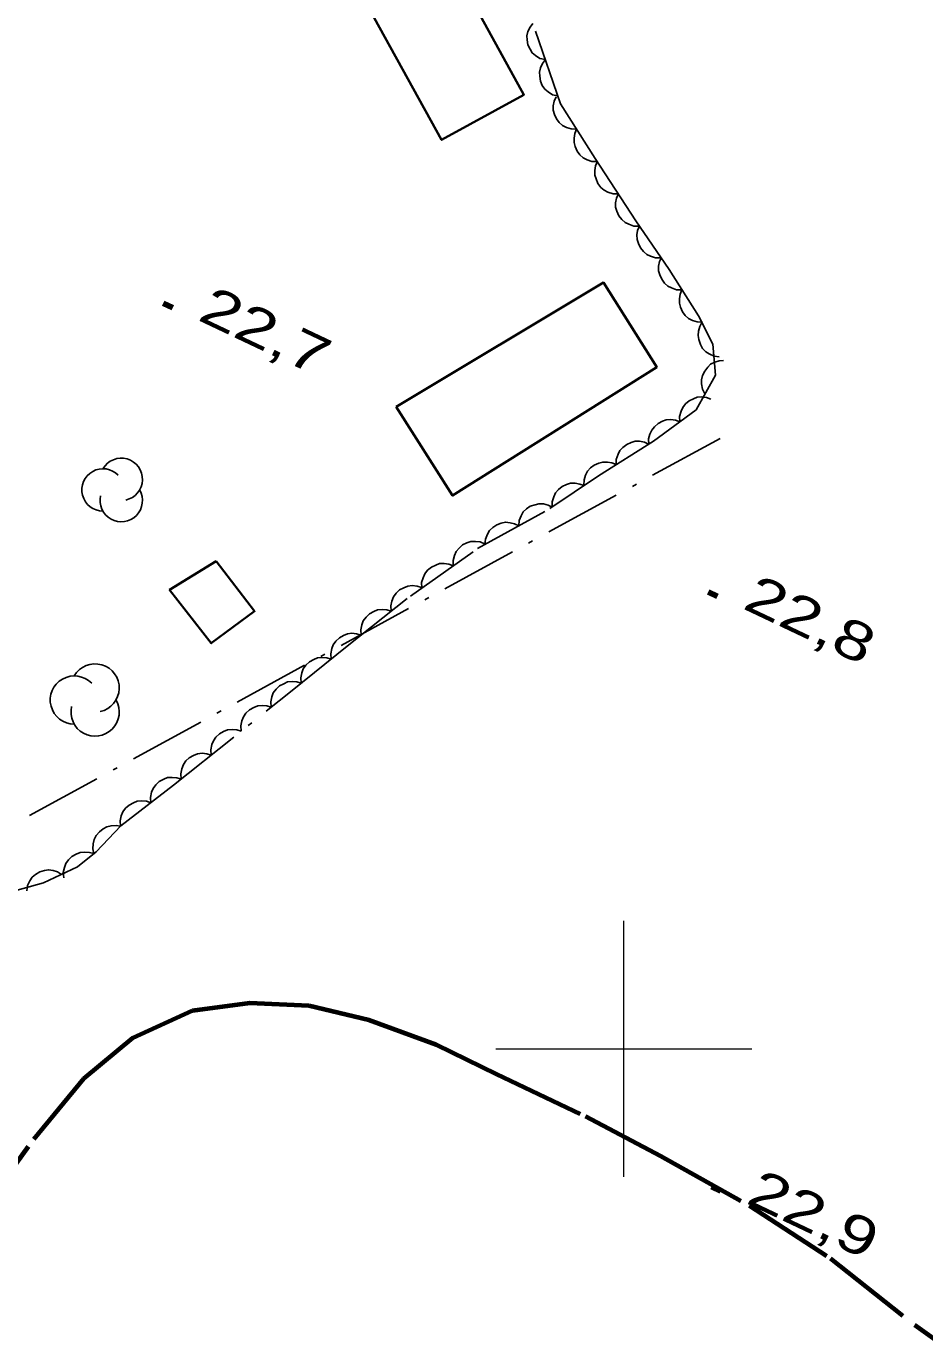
# Model space of a CAD drawing. Extents: x 356765 to 358572, y 5103174 to 5104650.
# Drawn here: x 357076.7 to 357111.7, y 5104088.5 to 5104139.9 of the extents above; entities that cross this region are included whole.
import ezdxf

# ---------------------------------------------------------------- set-up
doc = ezdxf.new("R2010")
doc.units = 0
doc.header["$LTSCALE"] = 0.6
doc.linetypes.add('DOT_DASHED', pattern=[7.7, 5, -1.2, 0.3, -1.2])
doc.linetypes.add('LONG_DASHED', pattern=[7.5, 6, -1.5])
for name, color, linetype, lineweight in [('22', 7, 'Continuous', 35), ('3', 7, 'Continuous', 140), ('31', 7, 'Continuous', 70), ('41', 7, 'DOT_DASHED', 25), ('44', 7, 'Continuous', 25), ('61', 7, 'Continuous', 13)]:
    doc.layers.add(name, color=color, linetype=linetype, lineweight=lineweight)

msp = doc.modelspace()

# ---------------------------------------------------------------- linework, layer by layer
at = {"layer": '22', "linetype": 'LONG_DASHED', "lineweight": 70}
msp.add_lwpolyline([(357070.45, 5104087.71), (357072.96, 5104090.8), (357074.65, 5104093.26), (357076.97, 5104096.47), (357078.92, 5104098.83), (357080.84, 5104100.43), (357083.17, 5104101.49), (357085.4, 5104101.79), (357087.7, 5104101.69), (357090.05, 5104101.13), (357092.68, 5104100.16), (357095.05, 5104099.01), (357098.51, 5104097.36), (357101.43, 5104095.82), (357104.9, 5104093.87), (357108.07, 5104091.8), (357111.35, 5104089.21), (357113.03, 5104088.01)], dxfattribs=at)
at = {"layer": '3'}
for p, q in [((357082.02, 5104129.12), (357082.38, 5104128.95)), ((357103.29, 5104117.85), (357103.65, 5104117.68)), ((357103.42, 5104094.62), (357103.78, 5104094.45))]:
    msp.add_line(p, q, dxfattribs=at)
at = {"layer": '31', "lineweight": 35}
for points in [[(357089.36, 5104141.91), (357092.89, 5104135.5), (357096.1, 5104137.27), (357092.58, 5104143.67), (357089.36, 5104141.91)], [(357091.11, 5104125.08), (357099.21, 5104129.93), (357101.29, 5104126.63), (357093.32, 5104121.61), (357091.11, 5104125.08)], [(357084.09, 5104119.05), (357085.59, 5104117.09), (357083.9, 5104115.84), (357082.27, 5104117.92), (357084.09, 5104119.05)]]:
    msp.add_lwpolyline(points, close=True, dxfattribs=at)
at = {"layer": '41'}
msp.add_line((357103.76, 5104123.84), (357040.83, 5104089.45), dxfattribs=at)
at = {"layer": '44', "linetype": 'DOT_DASHED'}
msp.add_lwpolyline([(357075.25, 5104105.89), (357077.35, 5104106.48), (357078.68, 5104107.11), (357079.4, 5104107.69), (357080.37, 5104108.71), (357082.43, 5104110.3), (357087.05, 5104113.99), (357089.2, 5104115.72), (357091.67, 5104117.68), (357094.29, 5104119.54), (357097.12, 5104121.1), (357099.02, 5104122.38), (357101.16, 5104123.74), (357102.83, 5104124.96), (357103.58, 5104126.31), (357103.48, 5104127.53), (357102.92, 5104128.63), (357101.77, 5104130.44), (357100.47, 5104132.34), (357098.89, 5104134.78), (357097.53, 5104136.91), (357096.11, 5104141.03)], dxfattribs=at)
at = {"layer": '44'}
for points in [[(357096.94, 5104138.64), (357096.73, 5104138.69), (357096.56, 5104138.8), (357096.43, 5104138.9), (357096.34, 5104139.05), (357096.26, 5104139.22), (357096.23, 5104139.41), (357096.22, 5104139.57), (357096.26, 5104139.74), (357096.34, 5104139.91), (357096.45, 5104140.05)], [(357097.42, 5104137.22), (357097.22, 5104137.27), (357097.05, 5104137.38), (357096.92, 5104137.48), (357096.82, 5104137.63), (357096.75, 5104137.8), (357096.72, 5104137.99), (357096.71, 5104138.15), (357096.75, 5104138.32), (357096.83, 5104138.49), (357096.94, 5104138.64)], [(357098.16, 5104135.92), (357097.95, 5104135.93), (357097.76, 5104135.99), (357097.61, 5104136.06), (357097.48, 5104136.18), (357097.37, 5104136.33), (357097.3, 5104136.5), (357097.25, 5104136.66), (357097.25, 5104136.84), (357097.28, 5104137.02), (357097.36, 5104137.18)], [(357098.97, 5104134.66), (357098.76, 5104134.66), (357098.57, 5104134.73), (357098.42, 5104134.8), (357098.29, 5104134.92), (357098.18, 5104135.06), (357098.1, 5104135.24), (357098.06, 5104135.4), (357098.06, 5104135.57), (357098.09, 5104135.75), (357098.16, 5104135.92)], [(357099.79, 5104133.4), (357099.58, 5104133.4), (357099.38, 5104133.46), (357099.23, 5104133.54), (357099.1, 5104133.65), (357098.99, 5104133.8), (357098.92, 5104133.98), (357098.87, 5104134.13), (357098.87, 5104134.31), (357098.9, 5104134.49), (357098.97, 5104134.66)], [(357100.6, 5104132.14), (357100.39, 5104132.14), (357100.2, 5104132.21), (357100.05, 5104132.28), (357099.92, 5104132.39), (357099.81, 5104132.54), (357099.73, 5104132.72), (357099.68, 5104132.87), (357099.68, 5104133.05), (357099.72, 5104133.23), (357099.79, 5104133.4)], [(357101.45, 5104130.9), (357101.24, 5104130.9), (357101.05, 5104130.96), (357100.9, 5104131.03), (357100.77, 5104131.14), (357100.65, 5104131.29), (357100.57, 5104131.46), (357100.52, 5104131.61), (357100.51, 5104131.79), (357100.54, 5104131.97), (357100.61, 5104132.14)], [(357102.27, 5104129.65), (357102.06, 5104129.65), (357101.87, 5104129.72), (357101.72, 5104129.79), (357101.59, 5104129.91), (357101.48, 5104130.06), (357101.41, 5104130.23), (357101.36, 5104130.39), (357101.36, 5104130.57), (357101.4, 5104130.75), (357101.47, 5104130.91)], [(357103.08, 5104128.38), (357102.87, 5104128.39), (357102.68, 5104128.45), (357102.53, 5104128.53), (357102.4, 5104128.64), (357102.29, 5104128.79), (357102.21, 5104128.97), (357102.17, 5104129.12), (357102.17, 5104129.3), (357102.2, 5104129.48), (357102.27, 5104129.65)], [(357103.73, 5104127.03), (357103.53, 5104127.06), (357103.34, 5104127.14), (357103.2, 5104127.23), (357103.08, 5104127.36), (357102.99, 5104127.51), (357102.93, 5104127.7), (357102.9, 5104127.86), (357102.92, 5104128.03), (357102.97, 5104128.21), (357103.05, 5104128.37)], [(357103.17, 5104125.58), (357103.08, 5104125.77), (357103.04, 5104125.97), (357103.04, 5104126.13), (357103.08, 5104126.3), (357103.16, 5104126.47), (357103.28, 5104126.62), (357103.39, 5104126.74), (357103.55, 5104126.82), (357103.72, 5104126.87), (357103.9, 5104126.89)], [(357102.19, 5104124.49), (357102.18, 5104124.7), (357102.24, 5104124.9), (357102.3, 5104125.05), (357102.41, 5104125.19), (357102.55, 5104125.31), (357102.72, 5104125.39), (357102.87, 5104125.45), (357103.05, 5104125.46), (357103.23, 5104125.44), (357103.4, 5104125.38)], [(357100.98, 5104123.61), (357100.97, 5104123.82), (357101.02, 5104124.01), (357101.09, 5104124.17), (357101.2, 5104124.3), (357101.34, 5104124.42), (357101.51, 5104124.51), (357101.66, 5104124.57), (357101.84, 5104124.58), (357102.02, 5104124.55), (357102.19, 5104124.49)], [(357099.71, 5104122.82), (357099.71, 5104123.02), (357099.78, 5104123.22), (357099.85, 5104123.37), (357099.97, 5104123.49), (357100.12, 5104123.61), (357100.29, 5104123.68), (357100.45, 5104123.73), (357100.62, 5104123.73), (357100.81, 5104123.69), (357100.97, 5104123.62)], [(357098.44, 5104122.01), (357098.45, 5104122.22), (357098.51, 5104122.41), (357098.58, 5104122.56), (357098.7, 5104122.69), (357098.85, 5104122.8), (357099.03, 5104122.88), (357099.18, 5104122.92), (357099.36, 5104122.92), (357099.54, 5104122.89), (357099.71, 5104122.82)], [(357097.21, 5104121.16), (357097.21, 5104121.37), (357097.27, 5104121.56), (357097.33, 5104121.71), (357097.45, 5104121.84), (357097.59, 5104121.96), (357097.77, 5104122.04), (357097.92, 5104122.09), (357098.1, 5104122.09), (357098.28, 5104122.06), (357098.45, 5104122)], [(357095.9, 5104120.43), (357095.92, 5104120.63), (357095.99, 5104120.82), (357096.07, 5104120.97), (357096.2, 5104121.09), (357096.35, 5104121.19), (357096.54, 5104121.25), (357096.69, 5104121.29), (357096.87, 5104121.28), (357097.05, 5104121.23), (357097.21, 5104121.15)], [(357094.58, 5104119.7), (357094.6, 5104119.91), (357094.68, 5104120.1), (357094.76, 5104120.24), (357094.89, 5104120.36), (357095.04, 5104120.47), (357095.22, 5104120.53), (357095.38, 5104120.57), (357095.56, 5104120.55), (357095.74, 5104120.51), (357095.9, 5104120.43)], [(357093.34, 5104118.87), (357093.34, 5104119.07), (357093.39, 5104119.27), (357093.46, 5104119.42), (357093.57, 5104119.56), (357093.71, 5104119.68), (357093.88, 5104119.76), (357094.03, 5104119.81), (357094.21, 5104119.82), (357094.39, 5104119.8), (357094.56, 5104119.73)], [(357092.12, 5104118), (357092.11, 5104118.21), (357092.17, 5104118.4), (357092.23, 5104118.55), (357092.34, 5104118.69), (357092.49, 5104118.81), (357092.66, 5104118.89), (357092.81, 5104118.95), (357092.99, 5104118.95), (357093.17, 5104118.93), (357093.34, 5104118.87)], [(357090.92, 5104117.09), (357090.91, 5104117.3), (357090.95, 5104117.49), (357091.01, 5104117.65), (357091.11, 5104117.79), (357091.25, 5104117.92), (357091.42, 5104118.01), (357091.57, 5104118.07), (357091.74, 5104118.09), (357091.93, 5104118.07), (357092.1, 5104118.02)], [(357089.75, 5104116.16), (357089.73, 5104116.36), (357089.78, 5104116.56), (357089.83, 5104116.72), (357089.94, 5104116.86), (357090.07, 5104116.99), (357090.24, 5104117.08), (357090.39, 5104117.14), (357090.57, 5104117.16), (357090.75, 5104117.14), (357090.92, 5104117.09)], [(357088.58, 5104115.22), (357088.56, 5104115.43), (357088.6, 5104115.63), (357088.66, 5104115.78), (357088.76, 5104115.92), (357088.9, 5104116.05), (357089.06, 5104116.14), (357089.21, 5104116.21), (357089.39, 5104116.23), (357089.57, 5104116.21), (357089.75, 5104116.16)], [(357087.41, 5104114.28), (357087.39, 5104114.49), (357087.43, 5104114.69), (357087.49, 5104114.84), (357087.59, 5104114.98), (357087.73, 5104115.11), (357087.9, 5104115.2), (357088.05, 5104115.27), (357088.22, 5104115.28), (357088.41, 5104115.27), (357088.58, 5104115.22)], [(357086.24, 5104113.34), (357086.22, 5104113.55), (357086.26, 5104113.75), (357086.32, 5104113.9), (357086.43, 5104114.04), (357086.56, 5104114.17), (357086.73, 5104114.26), (357086.88, 5104114.33), (357087.05, 5104114.34), (357087.24, 5104114.33), (357087.41, 5104114.28)], [(357085.07, 5104112.41), (357085.05, 5104112.61), (357085.09, 5104112.81), (357085.15, 5104112.97), (357085.25, 5104113.11), (357085.39, 5104113.24), (357085.56, 5104113.33), (357085.71, 5104113.39), (357085.88, 5104113.41), (357086.07, 5104113.39), (357086.24, 5104113.34)], [(357083.89, 5104111.47), (357083.88, 5104111.68), (357083.92, 5104111.88), (357083.98, 5104112.03), (357084.08, 5104112.17), (357084.22, 5104112.3), (357084.38, 5104112.39), (357084.53, 5104112.46), (357084.71, 5104112.47), (357084.89, 5104112.46), (357085.07, 5104112.41)], [(357082.72, 5104110.53), (357082.71, 5104110.74), (357082.75, 5104110.94), (357082.81, 5104111.1), (357082.91, 5104111.24), (357083.04, 5104111.36), (357083.21, 5104111.46), (357083.36, 5104111.52), (357083.54, 5104111.54), (357083.72, 5104111.52), (357083.89, 5104111.47)], [(357081.54, 5104109.61), (357081.53, 5104109.82), (357081.57, 5104110.02), (357081.63, 5104110.17), (357081.74, 5104110.31), (357081.87, 5104110.44), (357082.04, 5104110.53), (357082.19, 5104110.59), (357082.37, 5104110.6), (357082.55, 5104110.58), (357082.73, 5104110.53)], [(357080.35, 5104108.7), (357080.34, 5104108.9), (357080.38, 5104109.1), (357080.44, 5104109.26), (357080.55, 5104109.4), (357080.69, 5104109.52), (357080.86, 5104109.61), (357081.01, 5104109.67), (357081.18, 5104109.68), (357081.37, 5104109.67), (357081.54, 5104109.61)], [(357079.32, 5104107.61), (357079.27, 5104107.81), (357079.29, 5104108.01), (357079.33, 5104108.17), (357079.41, 5104108.33), (357079.53, 5104108.47), (357079.68, 5104108.59), (357079.82, 5104108.67), (357079.99, 5104108.71), (357080.18, 5104108.72), (357080.35, 5104108.69)], [(357078.14, 5104106.68), (357078.12, 5104106.88), (357078.17, 5104107.08), (357078.22, 5104107.24), (357078.33, 5104107.38), (357078.46, 5104107.51), (357078.63, 5104107.6), (357078.78, 5104107.67), (357078.95, 5104107.68), (357079.14, 5104107.67), (357079.31, 5104107.62)], [(357076.7, 5104106.17), (357076.73, 5104106.38), (357076.82, 5104106.56), (357076.91, 5104106.7), (357077.04, 5104106.81), (357077.2, 5104106.91), (357077.39, 5104106.96), (357077.55, 5104106.99), (357077.72, 5104106.96), (357077.9, 5104106.91), (357078.05, 5104106.81)]]:
    msp.add_lwpolyline(points, dxfattribs=at)
for centre, radius, start, end in [((357080.3857, 5104122.2427), 0.8277, 282.26917, 149.72626), ((357079.6739, 5104121.8288), 0.8277, 44.11537, 269.80396), ((357080.3857, 5104121.4149), 0.8277, 166.93686, 29.62122), ((357079.3634, 5104114.0923), 0.9419, 282.26917, 149.72626), ((357078.5534, 5104113.6214), 0.9419, 44.11537, 269.80396), ((357079.3634, 5104113.1505), 0.9419, 166.93686, 29.62122)]:
    msp.add_arc(centre, radius, start, end, dxfattribs=at)
at = {"layer": '61'}
for p, q in [((357100, 5104095), (357100, 5104105)), ((357095, 5104100), (357105, 5104100))]:
    msp.add_line(p, q, dxfattribs=at)

# ---------------------------------------------------------------- texts
at = {"layer": '3', "width": 1.35}
for s, p in [('22,7   ', (357083.32, 5104128.49)), ('22,8   ', (357104.59, 5104117.22)), ('22,9   ', (357104.72, 5104093.99))]:
    msp.add_text(s, height=1.5, rotation=334.619, dxfattribs=at).set_placement(p)

doc.saveas('drawing.dxf')
